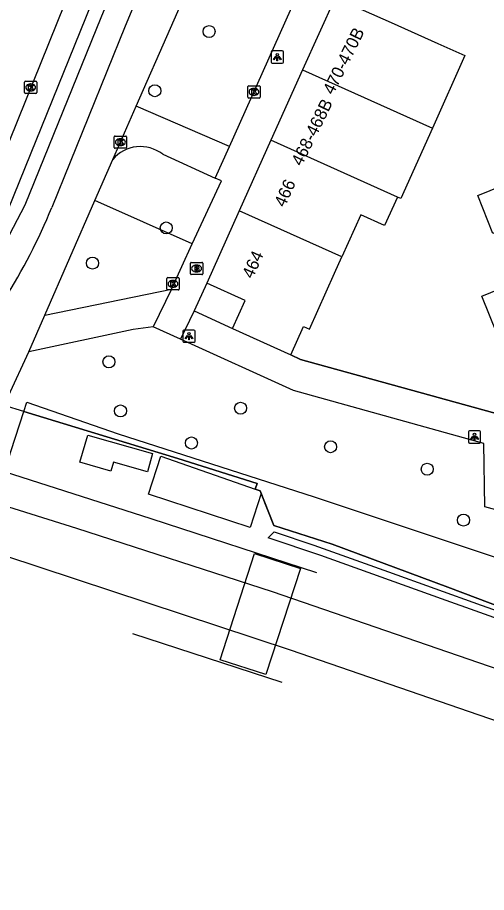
# Model space of a CAD drawing. Extents: x 162990 to 165007, y 383433 to 384336.
# Drawn here: x 163762.4 to 163800.5, y 383839.9 to 383911.1 of the extents above; entities that cross this region are included whole.
import ezdxf

# ---------------------------------------------------------------- set-up
doc = ezdxf.new("R2010")
doc.units = 0
for name, color, linetype in [('IMGEO_Boom', 7, 'Continuous'), ('IMGEO_Brandkraan', 7, 'Continuous'), ('IMGEO_Fietspad_open', 7, 'Continuous'), ('IMGEO_Geluidsscherm', 7, 'Continuous'), ('IMGEO_Groenvoorziening', 7, 'Continuous'), ('IMGEO_Hek', 7, 'Continuous'), ('IMGEO_Kolk', 7, 'Continuous'), ('IMGEO_Lichtpunt', 7, 'Continuous'), ('IMGEO_Muur', 7, 'Continuous'), ('IMGEO_Pand', 7, 'Continuous'), ('IMGEO_Pand_nummerreeks', 7, 'Continuous'), ('IMGEO_Pand_vergunning_verleend', 7, 'Continuous'), ('IMGEO_Parkeervlak_open', 7, 'Continuous'), ('IMGEO_Rijbaan_lokaal_gesloten', 7, 'Continuous'), ('IMGEO_Spoor', 7, 'Continuous'), ('IMGEO_Spoorbaan_gesloten', 7, 'Continuous'), ('IMGEO_Spoorbaan_halfverhard', 7, 'Continuous'), ('IMGEO_Voetpad_open', 7, 'Continuous')]:
    doc.layers.add(name, color=color, linetype=linetype)

msp = doc.modelspace()

# ---------------------------------------------------------------- linework, layer by layer
at = {"layer": 'IMGEO_Boom'}
for centre in [(163777.973, 383909.91), (163773.558, 383905.102), (163774.49, 383893.946), (163768.495, 383891.084), (163769.833, 383883.06), (163770.767, 383879.063), (163780.536, 383879.286), (163776.538, 383876.46), (163787.853, 383876.155), (163795.708, 383874.327), (163798.656, 383870.191)]:
    msp.add_circle(centre, 0.489, dxfattribs=at)
at = {"layer": 'IMGEO_Brandkraan'}
for p, q in [((163776.453, 383890.221), (163776.453, 383891.073)), ((163776.528, 383891.147), (163777.38, 383891.147)), ((163776.941, 383890.927), (163776.966, 383890.927)), ((163777.454, 383891.073), (163777.454, 383890.221)), ((163777.38, 383890.147), (163776.528, 383890.147)), ((163776.964, 383890.367), (163776.939, 383890.367))]:
    msp.add_line(p, q, dxfattribs=at)
for points in [[(163776.453, 383890.221), (163776.453, 383891.073)], [(163776.528, 383891.147), (163777.38, 383891.147)], [(163776.801, 383890.847), (163776.801, 383890.447), (163777.014, 383890.447)], [(163777.032, 383890.847), (163776.801, 383890.847)], [(163776.98, 383890.766), (163776.926, 383890.766), (163776.926, 383890.69)], [(163776.926, 383890.69), (163776.979, 383890.69)], [(163776.988, 383890.614), (163776.926, 383890.614), (163776.926, 383890.533)], [(163776.926, 383890.533), (163776.988, 383890.533)], [(163777.454, 383891.073), (163777.454, 383890.221)], [(163777.38, 383890.147), (163776.528, 383890.147)]]:
    msp.add_lwpolyline(points, dxfattribs=at)
for centre, radius, start, end in [((163776.53, 383891.071), 0.0765, 91.55205, 178.44795), ((163776.53, 383891.071), 0.0765, 91.55205, 178.44795), ((163776.981, 383890.728), 0.0379, 267.82845, 90.93552), ((163776.989, 383890.573), 0.0404, 269.87594, 90.50774), ((163777.02, 383890.698), 0.251, 268.66757, 293.53466), ((163777.036, 383890.702), 0.145, 59.4692, 91.53667), ((163777.061, 383890.749), 0.0922, 285.51372, 58.15012), ((163777.066, 383890.557), 0.105, 301.31148, 78.98903), ((163777.378, 383891.071), 0.0765, 1.55205, 88.44795), ((163777.378, 383891.071), 0.0765, 1.55205, 88.44795), ((163776.53, 383890.223), 0.0765, 181.55205, 268.44795), ((163776.53, 383890.223), 0.0765, 181.55205, 268.44795), ((163777.378, 383890.223), 0.0765, 271.55205, 358.44795), ((163777.378, 383890.223), 0.0765, 271.55205, 358.44795)]:
    msp.add_arc(centre, radius, start, end, dxfattribs=at)
for centre, major_axis, ratio, start_param, end_param in [((163776.94, 383890.647), (-0.387, 0.002), 0.722429, 4.712389, 7.853982), ((163776.965, 383890.647), (-0.39, 0.002), 0.717154, 1.570796, 4.712389)]:
    msp.add_ellipse(centre, major_axis=major_axis, ratio=ratio, start_param=start_param, end_param=end_param, dxfattribs=at)
at = {"layer": 'IMGEO_Fietspad_open'}
for points in [[(163791.65, 383961.052), (163780.183, 383936.438), (163779.432, 383934.804), (163773.298, 383920.997), (163769.172, 383911.032), (163762.996, 383895.792), (163759.509, 383889.159), (163757.08, 383883.986), (163754.892, 383878.688), (163753.427, 383875.029)], [(163793.546, 383960.135), (163782.132, 383935.646), (163781.333, 383933.941), (163775.275, 383920.253), (163771.153, 383910.346), (163765.179, 383895.611)]]:
    msp.add_lwpolyline(points, dxfattribs=at)
msp.add_arc((163719.213, 383914.45), 49.677, 328.00994, 337.71341, dxfattribs=at)
at = {"layer": 'IMGEO_Geluidsscherm'}
msp.add_lwpolyline([(163774.047, 383875.395), (163781.725, 383872.709), (163782.123, 383872.57), (163783.249, 383869.744), (163787.974, 383868.232), (163797.39, 383864.741), (163802.042, 383862.977), (163811.536, 383859.691), (163820.834, 383856.399), (163836.515, 383850.787), (163850.738, 383845.96), (163855.441, 383844.22), (163861.228, 383841.814), (163878.606, 383834.878)], dxfattribs=at)
at = {"layer": 'IMGEO_Groenvoorziening'}
for points in [[(163776.604, 383892.642), (163768.685, 383896.176)], [(163762.901, 383879.022), (163763.142, 383879.783), (163770.57, 383877.207), (163786.519, 383872.073), (163829.229, 383857.865), (163846.299, 383851.794), (163880.237, 383839.724), (163923.817, 383821.246), (163935.03, 383816.871), (163938.07, 383815.685), (164000, 383788.515), (164001.434, 383787.886), (164020.113, 383778.24), (164032.955, 383772.178), (164060.575, 383757.962), (164061.832, 383760.603)], [(163782.214, 383872.341), (163782.123, 383872.57), (163781.725, 383872.709)]]:
    msp.add_lwpolyline(points, dxfattribs=at)
at = {"layer": 'IMGEO_Hek'}
for points in [[(163786.726, 383865.892), (163773.267, 383870.305), (163761.346, 383874.116), (163761.892, 383875.837), (163762.901, 383879.022), (163775.421, 383875.198), (163781.885, 383873.168), (163781.725, 383872.709)], [(163771.745, 383860.975), (163783.89, 383857.018)]]:
    msp.add_lwpolyline(points, dxfattribs=at)
at = {"layer": 'IMGEO_Kolk'}
for p, q in [((163762.965, 383904.944), (163762.965, 383905.796)), ((163763.04, 383905.87), (163763.892, 383905.87)), ((163763.453, 383905.65), (163763.478, 383905.65)), ((163763.966, 383905.796), (163763.966, 383904.944)), ((163781.117, 383904.579), (163781.117, 383905.431)), ((163781.192, 383905.505), (163782.044, 383905.505)), ((163782.118, 383905.431), (163782.118, 383904.579)), ((163763.892, 383904.87), (163763.04, 383904.87)), ((163763.476, 383905.09), (163763.451, 383905.09)), ((163781.628, 383904.725), (163781.603, 383904.725)), ((163781.605, 383905.285), (163781.63, 383905.285)), ((163782.044, 383904.505), (163781.192, 383904.505)), ((163770.263, 383900.491), (163770.263, 383901.343)), ((163770.338, 383901.417), (163771.19, 383901.417)), ((163770.751, 383901.197), (163770.776, 383901.197)), ((163771.264, 383901.343), (163771.264, 383900.491)), ((163770.774, 383900.637), (163770.749, 383900.637)), ((163771.19, 383900.417), (163770.338, 383900.417)), ((163774.534, 383888.977), (163774.534, 383889.829)), ((163774.609, 383889.903), (163775.461, 383889.903)), ((163775.535, 383889.829), (163775.535, 383888.977)), ((163775.045, 383889.123), (163775.02, 383889.123)), ((163775.022, 383889.683), (163775.047, 383889.683)), ((163775.461, 383888.903), (163774.609, 383888.903))]:
    msp.add_line(p, q, dxfattribs=at)
for points in [[(163762.965, 383904.944), (163762.965, 383905.796)], [(163763.04, 383905.87), (163763.892, 383905.87)], [(163763.286, 383905.57), (163763.409, 383905.57), (163763.409, 383905.419), (163763.539, 383905.57), (163763.703, 383905.57), (163763.557, 383905.419), (163763.71, 383905.17), (163763.558, 383905.17), (163763.473, 383905.334), (163763.409, 383905.267), (163763.409, 383905.17), (163763.286, 383905.17), (163763.286, 383905.57)], [(163763.966, 383905.796), (163763.966, 383904.944)], [(163781.117, 383904.579), (163781.117, 383905.431)], [(163781.192, 383905.505), (163782.044, 383905.505)], [(163782.118, 383905.431), (163782.118, 383904.579)], [(163763.892, 383904.87), (163763.04, 383904.87)], [(163781.438, 383905.205), (163781.561, 383905.205), (163781.561, 383905.054), (163781.691, 383905.205), (163781.855, 383905.205), (163781.709, 383905.054), (163781.862, 383904.805), (163781.71, 383904.805), (163781.625, 383904.969), (163781.561, 383904.902), (163781.561, 383904.805), (163781.438, 383904.805), (163781.438, 383905.205)], [(163782.044, 383904.505), (163781.192, 383904.505)], [(163770.263, 383900.491), (163770.263, 383901.343)], [(163770.338, 383901.417), (163771.19, 383901.417)], [(163771.264, 383901.343), (163771.264, 383900.491)], [(163770.584, 383901.117), (163770.707, 383901.117), (163770.707, 383900.966), (163770.837, 383901.117), (163771.001, 383901.117), (163770.855, 383900.966), (163771.008, 383900.717), (163770.856, 383900.717), (163770.771, 383900.881), (163770.707, 383900.814), (163770.707, 383900.717), (163770.584, 383900.717), (163770.584, 383901.117)], [(163771.19, 383900.417), (163770.338, 383900.417)], [(163774.534, 383888.977), (163774.534, 383889.829)], [(163774.609, 383889.903), (163775.461, 383889.903)], [(163775.535, 383889.829), (163775.535, 383888.977)], [(163774.855, 383889.603), (163774.978, 383889.603), (163774.978, 383889.452), (163775.108, 383889.603), (163775.272, 383889.603), (163775.126, 383889.452), (163775.279, 383889.203), (163775.127, 383889.203), (163775.042, 383889.367), (163774.978, 383889.3), (163774.978, 383889.203), (163774.855, 383889.203), (163774.855, 383889.603)], [(163775.461, 383888.903), (163774.609, 383888.903)]]:
    msp.add_lwpolyline(points, dxfattribs=at)
for centre, start, end in [((163763.042, 383905.794), 91.55205, 178.44795), ((163763.042, 383905.794), 91.55205, 178.44795), ((163763.89, 383905.794), 1.55205, 88.44795), ((163763.89, 383905.794), 1.55205, 88.44795), ((163781.194, 383905.429), 91.55205, 178.44795), ((163781.194, 383905.429), 91.55205, 178.44795), ((163782.042, 383905.429), 1.55205, 88.44795), ((163782.042, 383905.429), 1.55205, 88.44795), ((163763.042, 383904.946), 181.55205, 268.44795), ((163763.042, 383904.946), 181.55205, 268.44795), ((163763.89, 383904.946), 271.55205, 358.44795), ((163763.89, 383904.946), 271.55205, 358.44795), ((163781.194, 383904.581), 181.55205, 268.44795), ((163781.194, 383904.581), 181.55205, 268.44795), ((163782.042, 383904.581), 271.55205, 358.44795), ((163782.042, 383904.581), 271.55205, 358.44795), ((163770.34, 383901.341), 91.55205, 178.44795), ((163770.34, 383901.341), 91.55205, 178.44795), ((163771.188, 383901.341), 1.55205, 88.44795), ((163771.188, 383901.341), 1.55205, 88.44795), ((163770.34, 383900.493), 181.55205, 268.44795), ((163770.34, 383900.493), 181.55205, 268.44795), ((163771.188, 383900.493), 271.55205, 358.44795), ((163771.188, 383900.493), 271.55205, 358.44795), ((163774.611, 383889.827), 91.55205, 178.44795), ((163774.611, 383889.827), 91.55205, 178.44795), ((163775.459, 383889.827), 1.55205, 88.44795), ((163775.459, 383889.827), 1.55205, 88.44795), ((163774.611, 383888.979), 181.55205, 268.44795), ((163774.611, 383888.979), 181.55205, 268.44795), ((163775.459, 383888.979), 271.55205, 358.44795), ((163775.459, 383888.979), 271.55205, 358.44795)]:
    msp.add_arc(centre, 0.0765, start, end, dxfattribs=at)
for centre, major_axis, ratio, start_param, end_param in [((163763.452, 383905.37), (-0.387, 0.002), 0.722429, 4.712389, 7.853982), ((163763.477, 383905.37), (-0.39, 0.002), 0.717154, 1.570796, 4.712389), ((163781.604, 383905.005), (-0.387, 0.002), 0.722429, 4.712389, 7.853982), ((163781.629, 383905.005), (-0.39, 0.002), 0.717154, 1.570796, 4.712389), ((163770.75, 383900.917), (-0.387, 0.002), 0.722429, 4.712389, 7.853982), ((163770.775, 383900.917), (-0.39, 0.002), 0.717154, 1.570796, 4.712389), ((163775.021, 383889.403), (-0.387, 0.002), 0.722429, 4.712389, 7.853982), ((163775.046, 383889.403), (-0.39, 0.002), 0.717154, 1.570796, 4.712389)]:
    msp.add_ellipse(centre, major_axis=major_axis, ratio=ratio, start_param=start_param, end_param=end_param, dxfattribs=at)
at = {"layer": 'IMGEO_Lichtpunt'}
for p, q in [((163783.918, 383908.335), (163783.11, 383908.335)), ((163783.918, 383908.335), (163783.11, 383908.335)), ((163783.016, 383908.24), (163783.016, 383907.433)), ((163783.016, 383908.24), (163783.016, 383907.433)), ((163784.012, 383907.433), (163784.012, 383908.24)), ((163784.012, 383907.433), (163784.012, 383908.24)), ((163783.11, 383907.339), (163783.918, 383907.339)), ((163783.11, 383907.339), (163783.918, 383907.339)), ((163775.836, 383885.545), (163775.836, 383884.738)), ((163775.836, 383885.545), (163775.836, 383884.738)), ((163776.738, 383885.64), (163775.93, 383885.64)), ((163776.738, 383885.64), (163775.93, 383885.64)), ((163776.832, 383884.738), (163776.832, 383885.545)), ((163776.832, 383884.738), (163776.832, 383885.545)), ((163775.93, 383884.644), (163776.738, 383884.644)), ((163775.93, 383884.644), (163776.738, 383884.644)), ((163799.051, 383877.359), (163799.051, 383876.552)), ((163799.051, 383877.359), (163799.051, 383876.552)), ((163799.953, 383877.454), (163799.145, 383877.454)), ((163799.953, 383877.454), (163799.145, 383877.454)), ((163800.047, 383876.552), (163800.047, 383877.359)), ((163800.047, 383876.552), (163800.047, 383877.359)), ((163799.145, 383876.458), (163799.953, 383876.458)), ((163799.145, 383876.458), (163799.953, 383876.458))]:
    msp.add_line(p, q, dxfattribs=at)
for points in [[(163783.39, 383907.904), (163783.429, 383907.876), (163783.241, 383907.614), (163783.203, 383907.641), (163783.39, 383907.904)], [(163783.492, 383907.856), (163783.539, 383907.856), (163783.539, 383907.534), (163783.492, 383907.534), (163783.492, 383907.856)], [(163783.602, 383907.876), (163783.64, 383907.903), (163783.827, 383907.641), (163783.788, 383907.613), (163783.602, 383907.876)], [(163776.21, 383885.209), (163776.249, 383885.181), (163776.061, 383884.919), (163776.023, 383884.946), (163776.21, 383885.209)], [(163776.312, 383885.161), (163776.359, 383885.161), (163776.359, 383884.839), (163776.312, 383884.839), (163776.312, 383885.161)], [(163776.422, 383885.181), (163776.46, 383885.208), (163776.647, 383884.946), (163776.608, 383884.918), (163776.422, 383885.181)], [(163799.425, 383877.023), (163799.464, 383876.995), (163799.276, 383876.733), (163799.238, 383876.76), (163799.425, 383877.023)], [(163799.527, 383876.975), (163799.574, 383876.975), (163799.574, 383876.653), (163799.527, 383876.653), (163799.527, 383876.975)], [(163799.637, 383876.995), (163799.675, 383877.022), (163799.862, 383876.76), (163799.823, 383876.732), (163799.637, 383876.995)]]:
    msp.add_lwpolyline(points, dxfattribs=at)
for centre in [(163783.515, 383908.038), (163776.335, 383885.343), (163799.55, 383877.157)]:
    msp.add_circle(centre, 0.0994, dxfattribs=at)
for centre, start, end in [((163783.11, 383908.24), 90, 180), ((163783.11, 383908.24), 90, 180), ((163783.918, 383908.24), 0, 90), ((163783.918, 383908.24), 0, 90), ((163783.11, 383907.433), 180, 270), ((163783.11, 383907.433), 180, 270), ((163783.918, 383907.433), 270, 0), ((163783.918, 383907.433), 270, 360), ((163775.93, 383885.545), 90, 180), ((163775.93, 383885.545), 90, 180), ((163776.738, 383885.545), 0, 90), ((163776.738, 383885.545), 0, 90), ((163775.93, 383884.738), 180, 270), ((163775.93, 383884.738), 180, 270), ((163776.738, 383884.738), 270, 0), ((163776.738, 383884.738), 270, 360), ((163799.145, 383877.359), 90, 180), ((163799.145, 383877.359), 90, 180), ((163799.953, 383877.359), 0, 90), ((163799.953, 383877.359), 0, 90), ((163799.145, 383876.552), 180, 270), ((163799.145, 383876.552), 180, 270), ((163799.953, 383876.552), 270, 0), ((163799.953, 383876.552), 270, 360)]:
    msp.add_arc(centre, 0.0946, start, end, dxfattribs=at)
at = {"layer": 'IMGEO_Muur'}
msp.add_lwpolyline([(163805.759, 383880.271), (163801.81, 383878.728), (163785.406, 383883.235), (163784.611, 383883.632)], dxfattribs=at)
at = {"layer": 'IMGEO_Pand'}
for points in [[(163788.217, 383912.69), (163785.571, 383906.798)], [(163788.217, 383912.69), (163792.779, 383910.642), (163796.555, 383908.947), (163798.772, 383907.952), (163796.126, 383902.059)], [(163785.571, 383906.798), (163782.999, 383901.07)], [(163785.571, 383906.798), (163796.126, 383902.059)], [(163796.126, 383902.059), (163793.554, 383896.331), (163793.277, 383896.455)], [(163782.999, 383901.07), (163780.426, 383895.34)], [(163793.277, 383896.455), (163782.999, 383901.07)], [(163793.277, 383896.455), (163792.241, 383894.148), (163790.301, 383895.019), (163788.764, 383891.596)], [(163780.426, 383895.34), (163777.782, 383889.452)], [(163788.764, 383891.596), (163780.426, 383895.34)], [(163784.611, 383883.632), (163785.642, 383885.928), (163786.122, 383885.713), (163788.171, 383890.275), (163788.764, 383891.596)], [(163779.876, 383885.758), (163780.905, 383888.05), (163777.782, 383889.452)], [(163804.132, 383884.476), (163802.059, 383883.64), (163800.142, 383888.396), (163802.216, 383889.232)], [(163779.876, 383885.758), (163784.611, 383883.632)]]:
    msp.add_lwpolyline(points, dxfattribs=at)
at = {"layer": 'IMGEO_Pand_vergunning_verleend'}
msp.add_lwpolyline([(163804.213, 383894.78), (163801.051, 383893.503), (163799.808, 383896.582), (163802.971, 383897.859)], dxfattribs=at)
at = {"layer": 'IMGEO_Parkeervlak_open'}
msp.add_lwpolyline([(163761.658, 383895.485), (163768.409, 383912.16), (163771.279, 383919.129), (163770.698, 383919.399)], dxfattribs=at)
at = {"layer": 'IMGEO_Rijbaan_lokaal_gesloten'}
msp.add_lwpolyline([(163795.079, 383975.769), (163789.902, 383964.696), (163786.656, 383957.76), (163776.508, 383936.015), (163770.272, 383921.927), (163766.204, 383912.135), (163758.54, 383893.202)], dxfattribs=at)
at = {"layer": 'IMGEO_Spoor'}
for points in [[(163711.098, 383886.583), (163738.85, 383878.416), (163767.191, 383869.544), (163783.087, 383864.395), (163809.961, 383855.143), (163826.892, 383849.133), (163844.814, 383842.61), (163875.401, 383830.856)], [(163718.441, 383880.353), (163738.829, 383874.363), (163758.351, 383868.284), (163784.552, 383859.656), (163812.02, 383850.197), (163835.796, 383841.636), (163859.382, 383832.867)]]:
    msp.add_lwpolyline(points, dxfattribs=at)
at = {"layer": 'IMGEO_Spoorbaan_gesloten'}
msp.add_lwpolyline([(163782.581, 383857.628), (163778.878, 383858.842), (163781.675, 383867.475), (163785.394, 383866.254), (163782.581, 383857.628)], dxfattribs=at)
at = {"layer": 'IMGEO_Spoorbaan_halfverhard'}
for points in [[(163762.901, 383879.022), (163761.318, 383879.505)], [(163781.725, 383872.709), (163781.885, 383873.168), (163775.421, 383875.198), (163762.901, 383879.022)], [(163772.957, 383874.128), (163770.203, 383874.914), (163769.992, 383874.173), (163767.473, 383874.892), (163768.105, 383877.107), (163773.378, 383875.603), (163772.957, 383874.128)], [(163782.214, 383872.341), (163781.311, 383869.592), (163773.034, 383872.311), (163774.047, 383875.395), (163781.725, 383872.709)], [(163878.606, 383834.878), (163861.228, 383841.814), (163855.441, 383844.22), (163850.738, 383845.96), (163836.515, 383850.787), (163820.834, 383856.399), (163811.536, 383859.691), (163802.042, 383862.977), (163797.39, 383864.741), (163787.974, 383868.232), (163783.249, 383869.744), (163782.214, 383872.341)], [(163852.121, 383844.294), (163845.11, 383846.729), (163832.424, 383851.195), (163815.197, 383857.267), (163796.878, 383863.779), (163787.055, 383867.312), (163782.762, 383868.752), (163783.261, 383869.243), (163786.475, 383868.16), (163792.556, 383865.978), (163800.087, 383863.28), (163808.79, 383860.202), (163819.561, 383856.383), (163826.91, 383853.804), (163837.203, 383850.176), (163846.239, 383846.996), (163859.103, 383842.175), (163867.653, 383838.805)]]:
    msp.add_lwpolyline(points, dxfattribs=at)
at = {"layer": 'IMGEO_Voetpad_open'}
for points in [[(163772.036, 383903.853), (163783.211, 383929.241)], [(163779.619, 383900.563), (163791.052, 383926.094)], [(163770.135, 383899.504), (163772.036, 383903.853)], [(163779.619, 383900.563), (163772.036, 383903.853)], [(163778.471, 383898), (163779.619, 383900.563)], [(163774.198, 383899.93), (163778.471, 383898)], [(163768.685, 383896.176), (163770.135, 383899.504)], [(163776.604, 383892.642), (163778.968, 383897.775), (163778.471, 383898)], [(163764.618, 383886.843), (163768.685, 383896.176)], [(163774.913, 383888.97), (163776.604, 383892.642)], [(163777.782, 383889.452), (163776.763, 383887.208)], [(163764.618, 383886.843), (163774.913, 383888.97)], [(163774.913, 383888.97), (163773.428, 383885.914)], [(163776.763, 383887.208), (163775.646, 383884.905)], [(163776.763, 383887.208), (163779.876, 383885.758)], [(163763.327, 383883.882), (163764.618, 383886.843)], [(163773.428, 383885.914), (163771.806, 383885.68), (163763.327, 383883.882)], [(163775.646, 383884.905), (163773.428, 383885.914)], [(163898.475, 383851.785), (163861.538, 383848.404), (163817.731, 383863.45), (163809.329, 383871.571), (163807.224, 383869.407), (163800.379, 383871.261), (163800.304, 383876.419), (163784.839, 383880.72), (163775.646, 383884.905)], [(163761.318, 383879.505), (163761.67, 383880.294), (163763.327, 383883.882)], [(163784.611, 383883.632), (163785.406, 383883.235), (163801.81, 383878.728), (163805.759, 383880.271)]]:
    msp.add_lwpolyline(points, dxfattribs=at)
msp.add_arc((163772.386, 383897.625), 2.932, 51.8289, 140.14213, dxfattribs=at)

# ---------------------------------------------------------------- texts
at = {"layer": 'IMGEO_Pand_nummerreeks'}
for s, rotation, p in [('470-470B', 63.66859, (163788.06, 383904.714)), ('468-468B', 63.83029, (163785.495, 383898.911)), ('466', 65.81758, (163784.123, 383895.565)), ('464', 65.81566, (163781.514, 383889.757))]:
    msp.add_text(s, height=1, rotation=rotation, dxfattribs=at).set_placement(p)

doc.saveas('drawing.dxf')
